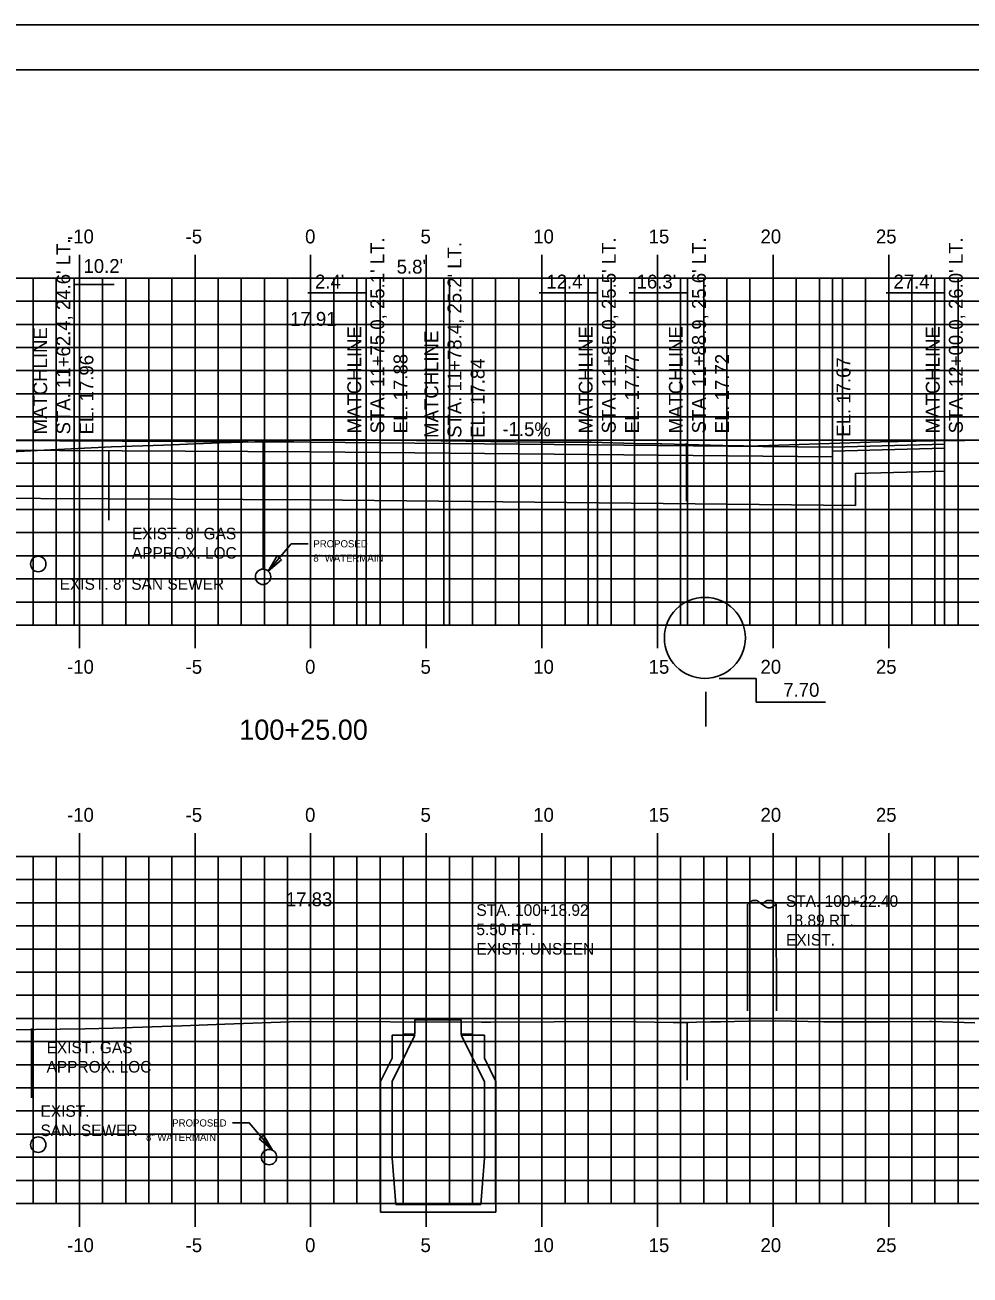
# Model space of a CAD drawing. Extents: x 1023237 to 1023407, y 394697 to 394807.
# Drawn here: x 1023307.3 to 1023348.2, y 394752.5 to 394806.5 of the extents above; entities that cross this region are included whole.
import ezdxf

# ---------------------------------------------------------------- set-up
doc = ezdxf.new("R2010")
doc.units = 0
for name, color, linetype in [('ANNOTATION', 7, 'Continuous'), ('BORDER', 7, 'Continuous'), ('D_Drainage_Culvert', 7, 'Continuous'), ('D_Drainage_Text', 7, 'Continuous'), ('D_Roadway_Centerline', 7, 'Continuous'), ('D_Roadway_Centerline_Text', 7, 'Continuous'), ('D_Roadway_Edge_TW', 7, 'Continuous'), ('D_Roadway_Pavement', 7, 'Continuous'), ('D_Roadway_SubGrade', 7, 'Continuous'), ('D_Text_Monospaced', 7, 'Continuous'), ('DIMENSIONS', 7, 'Continuous'), ('H_V ANNOTATION', 7, 'Continuous'), ('MAJOR', 7, 'Continuous'), ('MINOR', 7, 'Continuous'), ('p-water', 7, 'Continuous'), ('p-water-text', 7, 'Continuous'), ('PLOT BOUNDARY', 7, 'Continuous'), ('S_Drainage_MH', 7, 'Continuous'), ('S_Roadway_Centerline', 7, 'Continuous'), ('S_Roadway_Edge_Pavement', 7, 'Continuous'), ('S_Utilities_Pole_Power', 7, 'Continuous'), ('S_Utilities_UG_Gas_Line', 7, 'Continuous'), ('S_Utilities_UG_Sanitary_Sewer', 7, 'Continuous')]:
    doc.layers.add(name, color=color, linetype=linetype)

msp = doc.modelspace()

# ---------------------------------------------------------------- linework, layer by layer
at = {"layer": 'ANNOTATION'}
for p, q in [((1023311.161, 394795.335), (1023309.438, 394795.335)), ((1023323.069, 394795.61), (1023325.588, 394795.61)), ((1023319.538, 394794.966), (1023322.057, 394794.966)), ((1023329.545, 394794.966), (1023332.064, 394794.966)), ((1023333.444, 394794.966), (1023335.963, 394794.966)), ((1023344.556, 394794.966), (1023347.075, 394794.966)), ((1023336.751, 394777.718), (1023336.751, 394776.23))]:
    msp.add_line(p, q, dxfattribs=at)
at = {"layer": 'BORDER'}
msp.add_line((1023404.664, 394804.607), (1023244.664, 394804.607), dxfattribs=at)
at = {"layer": 'D_Drainage_Culvert'}
msp.add_circle((1023336.711, 394780.057), 1.752, dxfattribs=at)
at = {"layer": 'D_Drainage_Text'}
for p, q in [((1023337.336, 394778.307), (1023338.932, 394778.307)), ((1023338.932, 394777.283), (1023338.932, 394778.307)), ((1023338.932, 394777.283), (1023341.931, 394777.283))]:
    msp.add_line(p, q, dxfattribs=at)
at = {"layer": 'D_Roadway_Edge_TW'}
for p, q in [((1023297.301, 394788.633), (1023319.663, 394788.518)), ((1023319.663, 394788.518), (1023342.226, 394788.295))]:
    msp.add_line(p, q, dxfattribs=at)
at = {"layer": 'D_Roadway_Pavement'}
for p, q in [((1023319.663, 394788.101), (1023297.301, 394788.216)), ((1023342.226, 394787.878), (1023319.663, 394788.101))]:
    msp.add_line(p, q, dxfattribs=at)
at = {"layer": 'D_Roadway_SubGrade'}
msp.add_lwpolyline([(1023343.226, 394785.785), (1023319.663, 394786.018), (1023296.301, 394786.138)], dxfattribs=at)
at = {"layer": 'DIMENSIONS'}
for p, q in [((1023309.438, 394780.607), (1023309.438, 394795.607)), ((1023322.057, 394780.607), (1023322.057, 394795.607)), ((1023325.426, 394780.607), (1023325.426, 394795.607)), ((1023332.064, 394780.607), (1023332.064, 394795.607)), ((1023335.963, 394780.607), (1023335.963, 394795.607)), ((1023342.226, 394780.591), (1023342.226, 394795.591)), ((1023347.075, 394780.607), (1023347.075, 394795.607)), ((1023342.226, 394788.295), (1023347.075, 394788.427)), ((1023342.226, 394788.128), (1023347.075, 394788.26))]:
    msp.add_line(p, q, dxfattribs=at)
msp.add_lwpolyline([(1023343.226, 394785.785), (1023343.226, 394787.156), (1023347.075, 394787.26)], dxfattribs=at)
at = {"layer": 'MAJOR'}
for p, q in [((1023309.663, 394796.609), (1023309.663, 394795.607)), ((1023314.663, 394796.609), (1023314.663, 394795.607)), ((1023319.663, 394796.609), (1023319.663, 394795.607)), ((1023324.663, 394796.609), (1023324.663, 394795.607)), ((1023329.663, 394796.609), (1023329.663, 394795.607)), ((1023334.663, 394796.609), (1023334.663, 394795.607)), ((1023339.663, 394796.609), (1023339.663, 394795.607)), ((1023344.663, 394796.609), (1023344.663, 394795.607)), ((1023249.663, 394795.607), (1023389.663, 394795.607)), ((1023309.663, 394780.607), (1023309.663, 394795.607)), ((1023314.663, 394780.607), (1023314.663, 394795.607)), ((1023319.663, 394780.607), (1023319.663, 394795.607)), ((1023324.663, 394780.607), (1023324.663, 394795.607)), ((1023329.663, 394780.607), (1023329.663, 394795.607)), ((1023334.663, 394780.607), (1023334.663, 394795.607)), ((1023339.663, 394780.607), (1023339.663, 394795.607)), ((1023344.663, 394780.607), (1023344.663, 394795.607)), ((1023249.663, 394790.607), (1023389.663, 394790.607)), ((1023249.663, 394785.607), (1023389.663, 394785.607)), ((1023249.663, 394780.607), (1023389.663, 394780.607)), ((1023309.663, 394779.605), (1023309.663, 394780.607)), ((1023314.663, 394779.605), (1023314.663, 394780.607)), ((1023319.663, 394779.605), (1023319.663, 394780.607)), ((1023324.663, 394779.605), (1023324.663, 394780.607)), ((1023329.663, 394779.605), (1023329.663, 394780.607)), ((1023334.663, 394779.605), (1023334.663, 394780.607)), ((1023339.663, 394779.605), (1023339.663, 394780.607)), ((1023344.663, 394779.605), (1023344.663, 394780.607)), ((1023309.663, 394771.609), (1023309.663, 394770.607)), ((1023314.663, 394771.609), (1023314.663, 394770.607)), ((1023319.663, 394771.609), (1023319.663, 394770.607)), ((1023324.663, 394771.609), (1023324.663, 394770.607)), ((1023329.663, 394771.609), (1023329.663, 394770.607)), ((1023334.663, 394771.609), (1023334.663, 394770.607)), ((1023339.663, 394771.609), (1023339.663, 394770.607)), ((1023344.663, 394771.609), (1023344.663, 394770.607)), ((1023249.663, 394770.607), (1023389.663, 394770.607)), ((1023309.663, 394755.607), (1023309.663, 394770.607)), ((1023314.663, 394755.607), (1023314.663, 394770.607)), ((1023319.663, 394755.607), (1023319.663, 394770.607)), ((1023324.663, 394755.607), (1023324.663, 394770.607)), ((1023329.663, 394755.607), (1023329.663, 394770.607)), ((1023334.663, 394755.607), (1023334.663, 394770.607)), ((1023339.663, 394755.607), (1023339.663, 394770.607)), ((1023344.663, 394755.607), (1023344.663, 394770.607)), ((1023249.663, 394765.607), (1023389.663, 394765.607)), ((1023249.663, 394760.607), (1023389.663, 394760.607)), ((1023249.663, 394755.607), (1023389.663, 394755.607)), ((1023309.663, 394754.605), (1023309.663, 394755.607)), ((1023314.663, 394754.605), (1023314.663, 394755.607)), ((1023319.663, 394754.605), (1023319.663, 394755.607)), ((1023324.663, 394754.605), (1023324.663, 394755.607)), ((1023329.663, 394754.605), (1023329.663, 394755.607)), ((1023334.663, 394754.605), (1023334.663, 394755.607)), ((1023339.663, 394754.605), (1023339.663, 394755.607)), ((1023344.663, 394754.605), (1023344.663, 394755.607))]:
    msp.add_line(p, q, dxfattribs=at)
at = {"layer": 'MINOR'}
for p, q in [((1023307.663, 394780.607), (1023307.663, 394795.607)), ((1023308.663, 394780.607), (1023308.663, 394795.607)), ((1023310.663, 394780.607), (1023310.663, 394795.607)), ((1023311.663, 394780.607), (1023311.663, 394795.607)), ((1023312.663, 394780.607), (1023312.663, 394795.607)), ((1023313.663, 394780.607), (1023313.663, 394795.607)), ((1023315.663, 394780.607), (1023315.663, 394795.607)), ((1023316.663, 394780.607), (1023316.663, 394795.607)), ((1023317.663, 394780.607), (1023317.663, 394795.607)), ((1023318.663, 394780.607), (1023318.663, 394795.607)), ((1023320.663, 394780.607), (1023320.663, 394795.607)), ((1023321.663, 394780.607), (1023321.663, 394795.607)), ((1023322.663, 394780.607), (1023322.663, 394795.607)), ((1023323.663, 394780.607), (1023323.663, 394795.607)), ((1023325.663, 394780.607), (1023325.663, 394795.607)), ((1023326.663, 394780.607), (1023326.663, 394795.607)), ((1023327.663, 394780.607), (1023327.663, 394795.607)), ((1023328.663, 394780.607), (1023328.663, 394795.607)), ((1023330.663, 394780.607), (1023330.663, 394795.607)), ((1023331.663, 394780.607), (1023331.663, 394795.607)), ((1023332.663, 394780.607), (1023332.663, 394795.607)), ((1023333.663, 394780.607), (1023333.663, 394795.607)), ((1023335.663, 394780.607), (1023335.663, 394795.607)), ((1023336.663, 394780.607), (1023336.663, 394795.607)), ((1023337.663, 394780.607), (1023337.663, 394795.607)), ((1023338.663, 394780.607), (1023338.663, 394795.607)), ((1023340.663, 394780.607), (1023340.663, 394795.607)), ((1023341.663, 394780.607), (1023341.663, 394795.607)), ((1023342.663, 394780.607), (1023342.663, 394795.607)), ((1023343.663, 394780.607), (1023343.663, 394795.607)), ((1023345.663, 394780.607), (1023345.663, 394795.607)), ((1023346.663, 394780.607), (1023346.663, 394795.607)), ((1023347.663, 394780.607), (1023347.663, 394795.607)), ((1023249.663, 394794.607), (1023389.663, 394794.607)), ((1023249.663, 394793.607), (1023389.663, 394793.607)), ((1023249.663, 394792.607), (1023389.663, 394792.607)), ((1023249.663, 394791.607), (1023389.663, 394791.607)), ((1023249.663, 394789.607), (1023389.663, 394789.607)), ((1023249.663, 394788.607), (1023389.663, 394788.607)), ((1023249.663, 394787.607), (1023389.663, 394787.607)), ((1023249.663, 394786.607), (1023389.663, 394786.607)), ((1023249.663, 394784.607), (1023389.663, 394784.607)), ((1023249.663, 394783.607), (1023389.663, 394783.607)), ((1023249.663, 394782.607), (1023389.663, 394782.607)), ((1023249.663, 394781.607), (1023389.663, 394781.607)), ((1023307.663, 394755.607), (1023307.663, 394770.607)), ((1023308.663, 394755.607), (1023308.663, 394770.607)), ((1023310.663, 394755.607), (1023310.663, 394770.607)), ((1023311.663, 394755.607), (1023311.663, 394770.607)), ((1023312.663, 394755.607), (1023312.663, 394770.607)), ((1023313.663, 394755.607), (1023313.663, 394770.607)), ((1023315.663, 394755.607), (1023315.663, 394770.607)), ((1023316.663, 394755.607), (1023316.663, 394770.607)), ((1023317.663, 394755.607), (1023317.663, 394770.607)), ((1023318.663, 394755.607), (1023318.663, 394770.607)), ((1023320.663, 394755.607), (1023320.663, 394770.607)), ((1023321.663, 394755.607), (1023321.663, 394770.607)), ((1023322.663, 394755.607), (1023322.663, 394770.607)), ((1023323.663, 394755.607), (1023323.663, 394770.607)), ((1023325.663, 394755.607), (1023325.663, 394770.607)), ((1023326.663, 394755.607), (1023326.663, 394770.607)), ((1023327.663, 394755.607), (1023327.663, 394770.607)), ((1023328.663, 394755.607), (1023328.663, 394770.607)), ((1023330.663, 394755.607), (1023330.663, 394770.607)), ((1023331.663, 394755.607), (1023331.663, 394770.607)), ((1023332.663, 394755.607), (1023332.663, 394770.607)), ((1023333.663, 394755.607), (1023333.663, 394770.607)), ((1023335.663, 394755.607), (1023335.663, 394770.607)), ((1023336.663, 394755.607), (1023336.663, 394770.607)), ((1023337.663, 394755.607), (1023337.663, 394770.607)), ((1023338.663, 394755.607), (1023338.663, 394770.607)), ((1023340.663, 394755.607), (1023340.663, 394770.607)), ((1023341.663, 394755.607), (1023341.663, 394770.607)), ((1023342.663, 394755.607), (1023342.663, 394770.607)), ((1023343.663, 394755.607), (1023343.663, 394770.607)), ((1023345.663, 394755.607), (1023345.663, 394770.607)), ((1023346.663, 394755.607), (1023346.663, 394770.607)), ((1023347.663, 394755.607), (1023347.663, 394770.607)), ((1023249.663, 394769.607), (1023389.663, 394769.607)), ((1023249.663, 394768.607), (1023389.663, 394768.607)), ((1023249.663, 394767.607), (1023389.663, 394767.607)), ((1023249.663, 394766.607), (1023389.663, 394766.607)), ((1023249.663, 394764.607), (1023389.663, 394764.607)), ((1023249.663, 394763.607), (1023389.663, 394763.607)), ((1023249.663, 394762.607), (1023389.663, 394762.607)), ((1023249.663, 394761.607), (1023389.663, 394761.607)), ((1023249.663, 394759.607), (1023389.663, 394759.607)), ((1023249.663, 394758.607), (1023389.663, 394758.607)), ((1023249.663, 394757.607), (1023389.663, 394757.607)), ((1023249.663, 394756.607), (1023389.663, 394756.607))]:
    msp.add_line(p, q, dxfattribs=at)
at = {"layer": 'p-water'}
msp.add_line((1023317.605, 394783.028), (1023317.605, 394788.528), dxfattribs=at)
for centre in [(1023317.605, 394782.695), (1023317.865, 394757.614)]:
    msp.add_circle(centre, 0.333, dxfattribs=at)
at = {"layer": 'p-water-text'}
for points in [[(1023317.823, 394782.947), (1023318.827, 394784.124), (1023319.559, 394784.124)], [(1023318.012, 394757.913), (1023317.008, 394759.09), (1023316.276, 394759.09)]]:
    msp.add_lwpolyline(points, dxfattribs=at)
for points in [[(1023318.404, 394783.437), (1023318.214, 394783.599), (1023317.823, 394782.947)], [(1023317.43, 394758.403), (1023317.621, 394758.565), (1023318.012, 394757.913)]]:
    msp.add_lwpolyline(points, close=True, dxfattribs=at)
at = {"layer": 'PLOT BOUNDARY'}
msp.add_lwpolyline([(1023236.57, 394696.548), (1023406.57, 394696.548), (1023406.57, 394806.548), (1023236.57, 394806.548)], close=True, dxfattribs=at)
at = {"layer": 'S_Drainage_MH'}
for p, q in [((1023324.165, 394762.879), (1023323.181, 394762.879)), ((1023323.181, 394762.879), (1023323.181, 394761.895)), ((1023323.181, 394760.878), (1023324.165, 394762.879)), ((1023327.183, 394762.879), (1023326.166, 394762.879)), ((1023326.166, 394762.879), (1023327.183, 394760.878)), ((1023327.183, 394761.895), (1023327.183, 394762.879)), ((1023323.181, 394761.895), (1023322.688, 394760.878)), ((1023327.675, 394760.878), (1023327.183, 394761.895)), ((1023322.688, 394760.878), (1023322.688, 394755.235)), ((1023323.181, 394757.564), (1023323.181, 394760.878)), ((1023327.183, 394760.878), (1023327.183, 394757.564)), ((1023327.675, 394755.235), (1023327.675, 394760.878)), ((1023323.345, 394755.563), (1023323.181, 394757.564)), ((1023327.183, 394757.564), (1023327.019, 394755.563)), ((1023327.019, 394755.563), (1023323.345, 394755.563)), ((1023322.688, 394755.235), (1023327.675, 394755.235))]:
    msp.add_line(p, q, dxfattribs=at)
msp.add_lwpolyline([(1023326.658, 394762.921), (1023326.166, 394762.921), (1023326.166, 394763.544), (1023324.165, 394763.544), (1023324.165, 394762.921), (1023323.673, 394762.921)], dxfattribs=at)
at = {"layer": 'S_Roadway_Centerline'}
for points in [[(1023306.096, 394788.075), (1023311.046, 394788.308), (1023313.295, 394788.39), (1023315.725, 394788.489), (1023317.751, 394788.547), (1023319.712, 394788.616), (1023322.088, 394788.618), (1023329.582, 394788.516), (1023331.807, 394788.518), (1023333.673, 394788.459), (1023334.773, 394788.442), (1023334.852, 394788.44), (1023335.913, 394788.414), (1023338.004, 394788.363), (1023338.379, 394788.353), (1023338.549, 394788.349), (1023339.029, 394788.364), (1023344.312, 394788.535), (1023346.596, 394788.574), (1023349.311, 394788.598)], [(1023306.691, 394763.108), (1023309.89, 394763.162), (1023311.11, 394763.186), (1023314.095, 394763.295), (1023315.949, 394763.36), (1023319.16, 394763.48), (1023327.051, 394763.444), (1023327.155, 394763.447), (1023327.185, 394763.444), (1023327.244, 394763.444), (1023327.436, 394763.444), (1023332.945, 394763.473), (1023335.343, 394763.438), (1023335.816, 394763.431), (1023335.946, 394763.431), (1023336.009, 394763.431), (1023336.355, 394763.442), (1023336.961, 394763.462), (1023337.394, 394763.467), (1023338.592, 394763.483), (1023339.76, 394763.509), (1023341.862, 394763.463), (1023344.607, 394763.463), (1023346.432, 394763.469), (1023346.48, 394763.469), (1023346.526, 394763.468), (1023348.384, 394763.423)]]:
    msp.add_lwpolyline(points, dxfattribs=at)
at = {"layer": 'S_Roadway_Edge_Pavement'}
for p, q in [((1023335.913, 394788.473), (1023335.913, 394785.973)), ((1023335.946, 394763.434), (1023335.946, 394760.934))]:
    msp.add_line(p, q, dxfattribs=at)
at = {"layer": 'S_Utilities_Pole_Power'}
for p, q in [((1023338.553, 394763.932), (1023338.549, 394768.551)), ((1023338.553, 394768.551), (1023338.709, 394768.661)), ((1023339.021, 394768.661), (1023339.177, 394768.551)), ((1023339.334, 394768.661), (1023339.177, 394768.551)), ((1023339.177, 394768.551), (1023339.334, 394768.44)), ((1023339.803, 394768.551), (1023339.647, 394768.661)), ((1023339.647, 394768.44), (1023339.803, 394768.551)), ((1023339.803, 394763.932), (1023339.799, 394768.551))]:
    msp.add_line(p, q, dxfattribs=at)
for centre, start, end in [((1023338.865, 394768.441), 90, 125.2644), ((1023338.865, 394768.441), 54.7356, 90), ((1023339.49, 394768.441), 90, 125.2644), ((1023339.49, 394768.662), 234.7356, 270), ((1023339.49, 394768.441), 54.7356, 90), ((1023339.49, 394768.662), 270, 305.2644)]:
    msp.add_arc(centre, 0.271, start, end, dxfattribs=at)
at = {"layer": 'S_Utilities_UG_Gas_Line'}
for p, q in [((1023310.929, 394788.15), (1023310.929, 394785.15)), ((1023307.597, 394763.178), (1023307.597, 394760.178))]:
    msp.add_line(p, q, dxfattribs=at)
at = {"layer": 'S_Utilities_UG_Sanitary_Sewer'}
for centre in [(1023307.884, 394783.25), (1023307.881, 394758.15)]:
    msp.add_circle(centre, 0.333, dxfattribs=at)

# ---------------------------------------------------------------- texts
at = {"layer": 'ANNOTATION'}
for s, rotation, p in [("STA. 11+62.4, 24.6' LT.", 90, (1023309.267, 394788.851)), ("STA. 11+75.0, 25.1' LT.", 90, (1023322.849, 394788.896)), ("STA. 11+78.4, 25.2' LT.", 90, (1023326.183, 394788.7)), ("STA. 11+85.0, 25.5' LT.", 90, (1023332.856, 394788.896)), ("STA. 11+88.9, 25.6' LT.", 90, (1023336.756, 394788.896)), ("STA. 12+00.0, 26.0' LT.", 90, (1023347.867, 394788.896)), ('MATCHLINE', 90, (1023308.267, 394788.851)), ('MATCHLINE', 90, (1023321.849, 394788.896)), ('MATCHLINE', 90, (1023325.183, 394788.7)), ('MATCHLINE', 90, (1023331.856, 394788.896)), ('MATCHLINE', 90, (1023335.756, 394788.896)), ('MATCHLINE', 90, (1023346.867, 394788.896)), ('EL. 17.96', 90, (1023310.267, 394788.851)), ('EL. 17.88', 90, (1023323.849, 394788.896)), ('EL. 17.84', 90, (1023327.183, 394788.7)), ('EL. 17.77', 90, (1023333.856, 394788.896)), ('EL. 17.72', 90, (1023337.756, 394788.896)), ('EL. 17.67', 90, (1023343.007, 394788.751)), ('-1.5%', 359.1499, (1023327.951, 394788.795))]:
    msp.add_text(s, height=0.6, rotation=rotation, dxfattribs=at).set_placement(p)
for s, p in [("10.2'", (1023309.838, 394795.829)), ("5.8'", (1023323.383, 394795.802)), ("2.4'", (1023319.851, 394795.157)), ("12.4'", (1023329.858, 394795.157)), ("16.3'", (1023333.758, 394795.157)), ("27.4'", (1023344.869, 394795.157))]:
    msp.add_text(s, height=0.6, dxfattribs=at).set_placement(p)
at = {"layer": 'D_Drainage_Text'}
msp.add_text('7.70', height=0.6, dxfattribs=at).set_placement((1023340.103, 394777.512))
at = {"layer": 'D_Roadway_Centerline'}
for s, p in [('C', (1023319.658, 394788.518)), ('L', (1023319.663, 394788.51)), ('C', (1023319.658, 394763.432)), ('L', (1023319.663, 394763.424))]:
    msp.add_text(s, height=0.0146, dxfattribs=at).set_placement(p)
at = {"layer": 'D_Roadway_Centerline_Text'}
for s, p in [('17.91', (1023318.775, 394793.544)), ('17.83', (1023318.59, 394768.458))]:
    msp.add_text(s, height=0.6, dxfattribs=at).set_placement(p)
at = {"layer": 'D_Text_Monospaced'}
for s, height, p in [('EXIST. 8" GAS', 0.49998, (1023311.933, 394784.315)), ('APPROX. LOC', 0.49998, (1023311.933, 394783.481)), ('EXIST. 8" SAN SEWER', 0.49998, (1023308.808, 394782.137)), ('STA. 100+22.40', 0.49998, (1023340.219, 394768.43)), ('STA. 100+18.92', 0.49998, (1023326.832, 394768.042)), ('18.89 RT.', 0.5, (1023340.219, 394767.596)), ('5.50 RT.', 0.5, (1023326.832, 394767.208)), ('EXIST. ', 0.5, (1023340.219, 394766.756)), ('EXIST. UNSEEN', 0.49998, (1023326.832, 394766.368)), ('EXIST. GAS', 0.5, (1023308.242, 394762.102)), ('APPROX. LOC', 0.49998, (1023308.242, 394761.269)), ('EXIST. ', 0.5, (1023307.98, 394759.355)), ('SAN. SEWER', 0.5, (1023307.98, 394758.522))]:
    msp.add_text(s, height=height, dxfattribs=at).set_placement(p)
at = {"layer": 'H_V ANNOTATION'}
for s, height, p in [('-10', 0.6, (1023309.128, 394797.107)), ('-5', 0.6, (1023314.254, 394797.107)), ('0', 0.6, (1023319.422, 394797.107)), ('5', 0.6, (1023324.414, 394797.107)), ('10', 0.6, (1023329.289, 394797.107)), ('15', 0.6, (1023334.281, 394797.107)), ('20', 0.6, (1023339.117, 394797.107)), ('25', 0.6, (1023344.109, 394797.107)), ('-10', 0.6, (1023309.128, 394778.507)), ('-5', 0.6, (1023314.254, 394778.507)), ('0', 0.6, (1023319.422, 394778.507)), ('5', 0.6, (1023324.414, 394778.507)), ('10', 0.6, (1023329.289, 394778.507)), ('15', 0.6, (1023334.281, 394778.507)), ('20', 0.6, (1023339.117, 394778.507)), ('25', 0.6, (1023344.109, 394778.507)), ('100+25.00', 0.875, (1023316.573, 394775.65)), ('-10', 0.6, (1023309.128, 394772.107)), ('-5', 0.6, (1023314.254, 394772.107)), ('0', 0.6, (1023319.422, 394772.107)), ('5', 0.6, (1023324.414, 394772.107)), ('10', 0.6, (1023329.289, 394772.107)), ('15', 0.6, (1023334.281, 394772.107)), ('20', 0.6, (1023339.117, 394772.107)), ('25', 0.6, (1023344.109, 394772.107)), ('-10', 0.6, (1023309.128, 394753.507)), ('-5', 0.6, (1023314.254, 394753.507)), ('0', 0.6, (1023319.422, 394753.507)), ('5', 0.6, (1023324.414, 394753.507)), ('10', 0.6, (1023329.289, 394753.507)), ('15', 0.6, (1023334.281, 394753.507)), ('20', 0.6, (1023339.117, 394753.507)), ('25', 0.6, (1023344.109, 394753.507))]:
    msp.add_text(s, height=height, dxfattribs=at).set_placement(p)
at = {"layer": 'p-water-text'}
for s, p in [('PROPOSED ', (1023319.78, 394783.97)), ('8" WATERMAIN', (1023319.78, 394783.35)), ('PROPOSED ', (1023313.678, 394758.936)), ('8" WATERMAIN', (1023312.542, 394758.316))]:
    msp.add_text(s, height=0.31, dxfattribs=at).set_placement(p)

doc.saveas('drawing.dxf')
